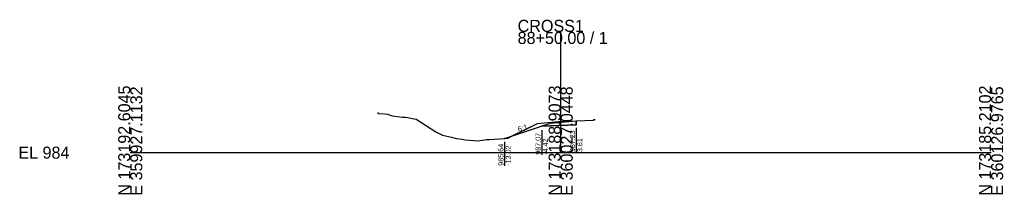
# Model space of a CAD drawing. Extents: x -26 to 1403, y -10 to 11027.
# Drawn here: x -25.7 to 202.8, y 3490.3 to 3530.9 of the extents above; entities that cross this region are included whole.
import ezdxf

# ---------------------------------------------------------------- set-up
doc = ezdxf.new("R2010")
doc.units = 0
for name, color, linetype in [('Default', 7, 'Continuous'), ('P_E_XS_Ground', 7, 'Continuous'), ('P_XS', 7, 'Continuous'), ('P_XS_EAR_CommonGrnd', 7, 'Continuous'), ('P_XS_Lane', 7, 'Continuous'), ('P_XS_Rock', 7, 'Continuous')]:
    doc.layers.add(name, color=color, linetype=linetype)

msp = doc.modelspace()

# ---------------------------------------------------------------- linework, layer by layer
at = {"layer": 'Default'}
for p, q in [((100, 3500), (100, 3528.07)), ((0, 3500), (100, 3500)), ((100, 3500), (200, 3500))]:
    msp.add_line(p, q, dxfattribs=at)
at = {"layer": 'P_E_XS_Ground'}
for p, q in [((57.43, 3509.36), (57.56, 3509.1)), ((57.56, 3509.1), (59.09, 3509.04)), ((59.09, 3509.04), (59.77, 3508.98)), ((59.77, 3508.98), (60.87, 3508.52)), ((60.87, 3508.52), (63.25, 3508.28)), ((63.25, 3508.28), (63.92, 3508.22)), ((63.92, 3508.22), (64.39, 3508.18)), ((64.39, 3508.18), (65.99, 3507.83)), ((65.99, 3507.83), (66.39, 3507.75)), ((66.39, 3507.75), (71.01, 3504.87)), ((94.5, 3506.73), (87.78, 3503.37)), ((99.5, 3507.13), (94.5, 3506.73)), ((107.61, 3507.45), (99.5, 3507.13)), ((107.61, 3507.67), (108.02, 3507.69)), ((107.61, 3507.67), (107.61, 3507.45)), ((71.01, 3504.87), (72.58, 3504.04)), ((72.58, 3504.04), (74.67, 3503.58)), ((74.67, 3503.58), (75.79, 3503.29)), ((75.79, 3503.29), (77.09, 3503.11)), ((77.09, 3503.11), (77.86, 3502.98)), ((77.86, 3502.98), (80.77, 3502.78)), ((80.77, 3502.78), (82.79, 3503.06)), ((82.79, 3503.06), (83.41, 3503.08)), ((83.41, 3503.08), (87.11, 3503.28)), ((87.11, 3503.28), (87.78, 3503.37))]:
    msp.add_line(p, q, dxfattribs=at)
at = {"layer": 'P_XS'}
for p, q in [((97.61, 3506.81), (95.58, 3506.14)), ((103.61, 3507.29), (97.61, 3506.81))]:
    msp.add_line(p, q, dxfattribs=at)
at = {"layer": 'P_XS_EAR_CommonGrnd'}
for points in [[(88.79, 3503.88), (95.58, 3506.14), (103.61, 3506.46), (103.61, 3507.29), (99.5, 3507.13), (94.5, 3506.73)], [(86.98, 3503.27), (88.79, 3503.88), (87.78, 3503.37), (87.11, 3503.28)]]:
    msp.add_lwpolyline(points, close=True, dxfattribs=at)
at = {"layer": 'P_XS_Lane'}
for p, q in [((86.98, 3503.27), (95.58, 3506.14)), ((103.61, 3506.46), (95.58, 3506.14)), ((103.61, 3507.29), (103.61, 3506.46))]:
    msp.add_line(p, q, dxfattribs=at)
at = {"layer": 'P_XS_Rock'}
for p, q in [((103.58, 3505.73), (103.58, 3500.13)), ((95.61, 3505.21), (95.61, 3499.52)), ((86.96, 3502.55), (86.96, 3496.96))]:
    msp.add_line(p, q, dxfattribs=at)

# ---------------------------------------------------------------- texts
at = {"layer": 'Default'}
for s, p in [('CROSS1', (90, 3528.07)), ('88+50.00 / 1', (90, 3525.27)), ('EL 984', (-26, 3498.6))]:
    msp.add_text(s, height=2.8, dxfattribs=at).set_placement(p)
for s, p in [('N 173192.6045', (0, 3490)), ('E 359927.1132', (2.8, 3490)), ('N 173188.9073', (100, 3490)), ('E 360027.0448', (102.8, 3490)), ('N 173185.2102', (200, 3490)), ('E 360126.9765', (202.8, 3490))]:
    msp.add_text(s, height=2.8, rotation=90, dxfattribs=at).set_placement(p)
at = {"layer": 'P_XS_Rock'}
for s, rotation, p in [('6:1', 18.4349, (90.26, 3504.8)), ('987.07', 90, (95.36, 3499.52)), ('987.23', 90, (103.33, 3500.13)), ('985.64', 90, (86.71, 3496.96)), ('-13.02', 90, (88.41, 3496.96)), ('-4.42', 90, (97.06, 3499.52)), ('3.61', 90, (105.03, 3500.13))]:
    msp.add_text(s, height=1.2, rotation=rotation, dxfattribs=at).set_placement(p)

doc.saveas('drawing.dxf')
